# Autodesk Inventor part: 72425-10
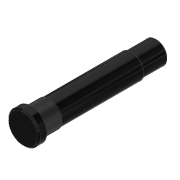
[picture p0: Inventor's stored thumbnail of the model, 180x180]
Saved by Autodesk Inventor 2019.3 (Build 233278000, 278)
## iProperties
Created: 2013-06
Part Number: 72425-10
Material: Ogólny
Document SubType Name: Modeling
Designer: CADENGINEERING4
Density: 1 g/cm^3
Appearance: Gładki — czarny
Author: CADENGINEERING4
Revision Number: ÈÎºÎ
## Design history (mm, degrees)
feature "ÊäÈë1"
node "Bryła1"
